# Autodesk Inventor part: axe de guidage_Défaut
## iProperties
Shininess: 64.0
Length Units: 11269
Angle Units: 11279
Time Units: 11290
Mass Units: 11283
Length Display Precision: 3
Angle Display Precision: 2
Compacted: True
Part Number: axe de guidage_Défaut
Document SubType Name: Modeling
Created: 2006-11
Material: Par défaut
Designer: profs_sti
Density: 0.0
Volumn: 0.0
Area: 0.0
PropertySet Name: Model Information
Control State: 0
Master: False
Checked Out: False
Author: profs_sti
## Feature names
1. Base1
